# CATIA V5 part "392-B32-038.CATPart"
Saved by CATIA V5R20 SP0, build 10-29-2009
Part number: 392-B32-038
Definition: NONE
Nomenclature: 392-B32-038
Source: Unknown
Description: 392-B32-038
Bounding box of the stored display mesh (mm): x 0 to 38, y -15.605 to 15.605, z -15.5 to 15.5
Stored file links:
  C:\Users\Utente\Desktop\IO LAVORO\3D X SITO CF\X SITO\3D files 392B\392-B32-038.CATPart
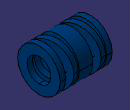
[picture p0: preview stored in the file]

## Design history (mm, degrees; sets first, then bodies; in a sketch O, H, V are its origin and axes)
Body1 "392-B32-038" (main body)
  Solid1: solid without history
